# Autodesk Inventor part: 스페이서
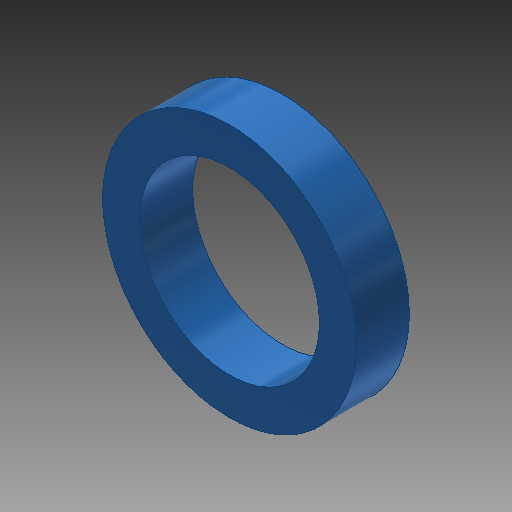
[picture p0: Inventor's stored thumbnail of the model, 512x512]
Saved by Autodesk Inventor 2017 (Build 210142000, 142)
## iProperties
Created: 2018-01
Part Number: 스페이서
Material: 스테인리스강
Document SubType Name: Modeling
Designer: mduedu
Density: 8.08 g/cm^3
Mass: 1.13832 g
Surface Area: 2.73711 cm^2
Volume: 0.140881 cm^3
Appearance: 청록색
Author: mduedu
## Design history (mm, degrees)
sketch "스케치1"
  geometry: C1 r 6 at (0, 0); C2 r 4.25 at (0, 0); 1 further point
  constraints: 2 centre point, 2 coincident
  dimensions: "d0" = 12 diameter of C1; "d1" = 8.5 diameter of C2
extrude "돌출1" new body sketch "스케치1" distance "d2" = 2.5; taper "d3" = 0 deg
node "솔리드1"
